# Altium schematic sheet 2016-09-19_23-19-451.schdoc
size 403 x 148 mm; SheetNumber: 1; SheetTotal: 1
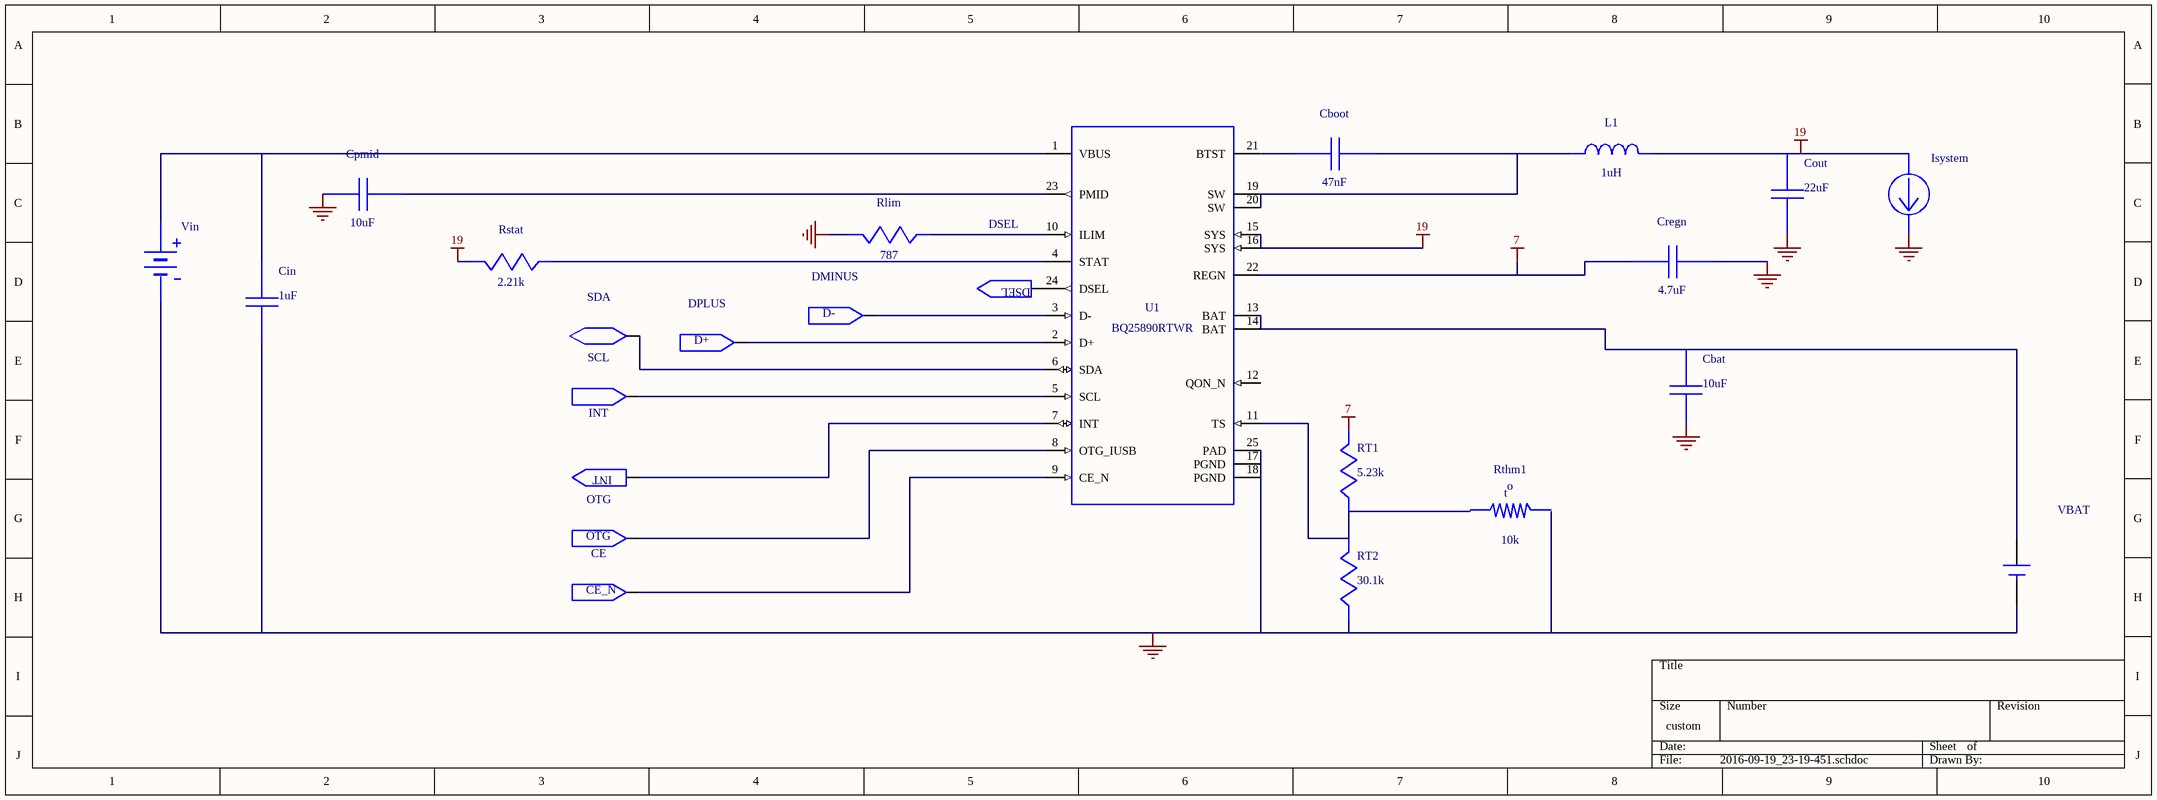
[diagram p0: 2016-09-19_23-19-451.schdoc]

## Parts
Cbat  value 10uF  (hidden comment: GRM219R60J106KE19D)
Cboot  value 47nF  (hidden comment: GRM155R61A473KA01D)
CE  WB_CE_N  (value not drawn)
Cin  value 1uF  (hidden comment: GRM188R61A105KA61D)
Cout  value 22uF  (hidden comment: LMK212BJ226MG-T)
Cpmid  value 10uF  (hidden comment: GRM21BR61A106KE19L)
Cregn  value 4.7uF  (hidden comment: GRM21BR61E475KA12L)
DMINUS  WB_DMINUS  (value not drawn)
DPLUS  WB_DPLUS  (value not drawn)
DSEL  WB_DSEL_R180  (value not drawn)
INT  WB_INT_R180  (value not drawn)
Isystem  WB_CURRENT_LOAD  (value not drawn)
L1  value 1uH  (hidden comment: 'VLF252012MT-1R0N')
OTG  WB_OTG  (value not drawn)
Rlim  value 787  (hidden comment: CRCW0402787RFKED)
Rstat  value 2.21k  (hidden comment: CRCW04022K21FKED)
RT1  value 5.23k  (hidden comment: CRCW04025K23FKED)
RT2  value 30.1k  (hidden comment: CRCW040230K1FKED)
Rthm1  value 10k  (hidden comment: NCP15XH103E03RC)
SCL  WB_I2C_SCL  (value not drawn)
SDA  WB_I2C_SDA  (value not drawn)
U1  BQ25890RTWR
VBAT  WB_BATTERY_SINGLE_USFP  (value not drawn)
Vin  WB_BATTERY  (value not drawn)

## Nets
0: Cin.2 Cout.2 Cpmid.2 Cregn.2 Isystem.2(-) Rlim.1 RT2.2 U1.17(PGND) U1.18(PGND) U1.25(PAD) VBAT.2(-) Vin.2(-)
7: Cregn.1 RT1.1 U1.22(REGN)
19: Cout.1 Isystem.1(+) L1.2 Rstat.1 U1.15(SYS) U1.16(SYS)
NetCbat_1: Cbat.1 U1.13(BAT) U1.14(BAT) VBAT.1(+)
NetCboot_1: Cboot.1 L1.1 U1.19(SW) U1.20(SW)
NetCboot_2: Cboot.2 U1.21(BTST)
NetCE_1: CE.1 U1.9(CE_N)
NetCin_1: Cin.1 U1.1(VBUS) Vin.1(+)
NetCpmid_1: Cpmid.1 U1.23(PMID)
NetDMINUS_1: DMINUS.1 U1.3(D-)
NetDPLUS_1: DPLUS.1 U1.2(D+)
NetDSEL_1: DSEL.1 U1.24(DSEL)
NetINT_1: INT.1 U1.7(INT)
NetOTG_1: OTG.1 U1.8(OTG_IUSB)
NetRlim_2: Rlim.2 U1.10(ILIM)
NetRstat_2: Rstat.2 U1.4(STAT)
NetRT1_2: RT1.2 RT2.1 U1.11(TS)
NetSCL_1: SCL.1 U1.5(SCL)
NetSDA_1: SDA.1 U1.6(SDA)

Not connected (* = marked no-connect by the designer): Cbat 2; Rthm1 1 2; U1 12(QON_N)

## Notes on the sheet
- (near DSEL) DSEL
- (near DPLUS) D+
- (near DMINUS) D-
- (near INT) INT
- (near Rthm1) o
- (near OTG) OTG
- (near Rthm1) t
- (near CE) CE_N
- Labels drawn without touching a wire or pin: 0

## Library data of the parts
Cbat = GRM219R60J106KE19D: GRM219R60J106KE1; Manufacturer Name: MuRata
Cboot = GRM155R61A473KA01D: GRM155R61A473KA0; Manufacturer Name: MuRata
Cin = GRM188R61A105KA61D: GRM188R61A105KA6; Manufacturer Name: MuRata
Cout = LMK212BJ226MG-T: Manufacturer Name: Taiyo Yuden
Cpmid = GRM21BR61A106KE19L: GRM21BR61A106KE1; Manufacturer Name: MuRata
Cregn = GRM21BR61E475KA12L: GRM21BR61E475KA1; Manufacturer Name: MuRata
L1 = 'VLF252012MT-1R0N': VLF252012MT-1R0N; Manufacturer Name: TDK
Rlim = CRCW0402787RFKED: Manufacturer Name: Vishay-Dale
Rstat = CRCW04022K21FKED: Manufacturer Name: Vishay-Dale
RT1 = CRCW04025K23FKED: Manufacturer Name: Vishay-Dale
RT2 = CRCW040230K1FKED: Manufacturer Name: Vishay-Dale
Rthm1 = NCP15XH103E03RC: Manufacturer Name: MuRata
U1 = BQ25890RTWR: Manufacturer Name: Texas Instruments
VBAT = WB_BATTERY_SINGLE_USFP: WB_BATTERY_SINGL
